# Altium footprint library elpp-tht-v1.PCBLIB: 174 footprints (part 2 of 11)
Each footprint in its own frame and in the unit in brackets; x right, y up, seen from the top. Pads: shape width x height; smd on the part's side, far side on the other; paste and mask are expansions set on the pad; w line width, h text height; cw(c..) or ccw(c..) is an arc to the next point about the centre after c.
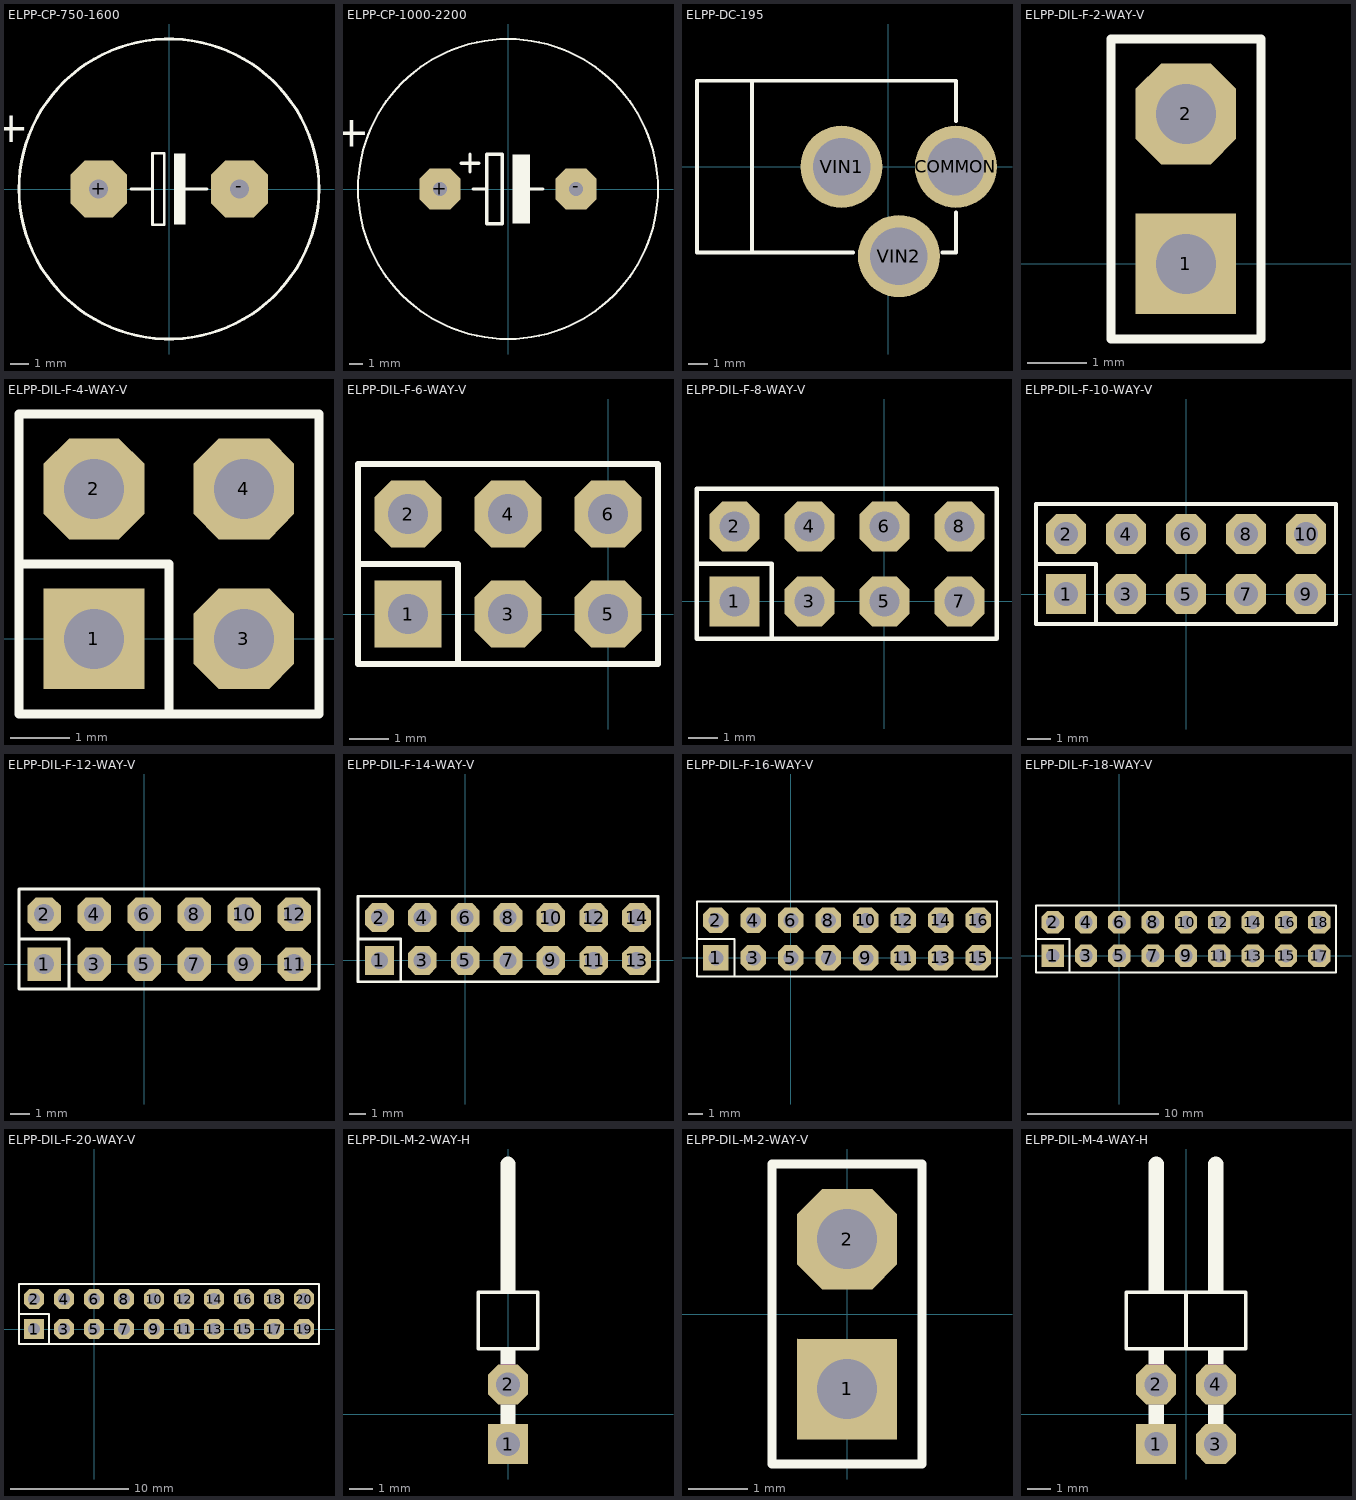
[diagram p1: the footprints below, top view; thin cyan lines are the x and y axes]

## ELPP-CP-750-1600 [mil]
pads (2):
  oct 119x119 hole 40: +(-147.64,0) -(148,0)
Top Overlay:
  circle w6: c0,0 r315
  rectangle: 10,-75 35,75
  lines w6: -80,0 -35,0 ; 25,0 80,0 ; -35,0 -35,75 -10,75 -10,-75 -35,-75 -35,0
  text "+" at -295,175 h108.5
Mechanical 2:
  text ">NAME" at -255,245 h42.5
Mechanical 4:
  text ">VALUE" at -150,-150 h42.5

## ELPP-CP-1000-2200 [mil]
pads (2):
  oct 119x119 hole 40: +(-196.85,0) -(197,0)
Top Overlay:
  circle w6: c0,0 r434
  rectangle: 13,-100 63,100
  lines w10: -135,75 -85,75 ; -110,50 -110,100 ; -100,0 -62,0 ; 25,0 100,0 ; -62,0 -62,100 -17,100 -17,-100 -62,-100 -62,0
  text "+" at -400,230 h155
Mechanical 2:
  text ">NAME" at -350,330 h42.5
Mechanical 4:
  text ">VALUE" at -150,-200 h42.5

## ELPP-DC-195 [mil]
pads (3):
  round 170 hole 119: COMMON(140,0) VIN1(-96.85,0) VIN2(22,-185.04)
Top Overlay:
  lines w8: -73.23,-177.17 -281.89,-177.17 ; 112,-177.17 140,-177.17 140,-94.49 ; 140,95 140,178 -281.89,178 ; -281.89,-177.17 -396.06,-177.17 -396.06,178 -281.89,178 ; -281.89,-177.17 -281.89,178
Mechanical 2:
  text ">NAME" at -200,200 h42.5
Mechanical 4:
  text ">VALUE" at -200,300 h42.5

## ELPP-DIL-F-2-WAY-V [mil]
pads (2):
  rect 67x67 hole 40: 1(-200,0)
  oct 67x67 hole 40: 2(-200,100)
Top Overlay:
  lines w6: -250,-50 -250,50 -250,150 -150,150 -150,-50 -250,-50
Mechanical 2:
  text ">NAME" at -250,185 h42.5
Mechanical 4:
  text ">VALUE" at -250,-135 h42.5
Mechanical 16:
  circle w16: c-200,100 r5
  circle w16: c-200,0 r5

## ELPP-DIL-F-4-WAY-V [mil]
pads (4):
  rect 67x67 hole 40: 1(-200,0)
  oct 67x67 hole 40: 2(-200,100) 3(-100,0) 4(-100,100)
Top Overlay:
  lines w6: -250,50 -250,-50 -150,-50 ; -250,50 -250,150 -50,150 -50,-50 -150,-50 ; -250,50 -150,50 -150,-50
Mechanical 2:
  text ">NAME" at -250,185 h42.5
Mechanical 4:
  text ">VALUE" at -250,-135 h42.5
Mechanical 16:
  circle w16: c-200,100 r5
  circle w16: c-200,0 r5
  circle w16: c-100,100 r5
  circle w16: c-100,0 r5

## ELPP-DIL-F-6-WAY-V [mil]
pads (6):
  rect 67x67 hole 40: 1(-200,0)
  oct 67x67 hole 40: 2(-200,100) 3(-100,0) 4(-100,100) 5(0,0) 6(0,100)
Top Overlay:
  lines w6: -250,50 -250,-50 -150,-50 ; -250,50 -250,150 50,150 50,-50 -150,-50 ; -250,50 -150,50 -150,-50
Mechanical 2:
  text ">NAME" at -250,185 h42.5
Mechanical 4:
  text ">VALUE" at -250,-135 h42.5
Mechanical 16:
  circle w16: c-200,100 r5
  circle w16: c-200,0 r5
  circle w16: c-100,100 r5
  circle w16: c-100,0 r5
  circle w16: c0,100 r5
  circle w16: c0,0 r5

## ELPP-DIL-F-8-WAY-V [mil]
pads (8):
  rect 67x67 hole 40: 1(-200,0)
  oct 67x67 hole 40: 2(-200,100) 3(-100,0) 4(-100,100) 5(0,0) 6(0,100) 7(100,0) 8(100,100)
Top Overlay:
  lines w6: -250,50 -250,-50 -150,-50 ; -250,50 -250,150 150,150 150,-50 -150,-50 ; -250,50 -150,50 -150,-50
Mechanical 2:
  text ">NAME" at -250,185 h42.5
Mechanical 4:
  text ">VALUE" at -250,-135 h42.5
Mechanical 16:
  circle w16: c-200,100 r5
  circle w16: c-200,0 r5
  circle w16: c-100,100 r5
  circle w16: c-100,0 r5
  circle w16: c0,100 r5
  circle w16: c0,0 r5
  circle w16: c100,100 r5
  circle w16: c100,0 r5

## ELPP-DIL-F-10-WAY-V [mil]
pads (10):
  rect 67x67 hole 40: 1(-200,0)
  oct 67x67 hole 40: 2(-200,100) 3(-100,0) 4(-100,100) 5(0,0) 6(0,100) 7(100,0) 8(100,100) 9(200,0) 10(200,100)
Top Overlay:
  lines w6: -250,50 -250,-50 -150,-50 ; -250,50 -250,150 250,150 250,-50 -150,-50 ; -250,50 -150,50 -150,-50
Mechanical 2:
  text ">NAME" at -250,185 h42.5
Mechanical 4:
  text ">VALUE" at -250,-135 h42.5
Mechanical 16:
  circle w16: c-200,100 r5
  circle w16: c-200,0 r5
  circle w16: c-100,100 r5
  circle w16: c-100,0 r5
  circle w16: c0,100 r5
  circle w16: c0,0 r5
  circle w16: c100,100 r5
  circle w16: c100,0 r5
  circle w16: c200,100 r5
  circle w16: c200,0 r5

## ELPP-DIL-F-12-WAY-V [mil]
pads (12):
  rect 67x67 hole 40: 1(-200,0)
  oct 67x67 hole 40: 2(-200,100) 3(-100,0) 4(-100,100) 5(0,0) 6(0,100) 7(100,0) 8(100,100) 9(200,0) 10(200,100) 11(300,0) 12(300,100)
Top Overlay:
  lines w6: -250,50 -250,-50 -150,-50 ; -250,50 -250,150 350,150 350,-50 -150,-50 ; -250,50 -150,50 -150,-50
Mechanical 2:
  text ">NAME" at -250,185 h42.5
Mechanical 4:
  text ">VALUE" at -250,-135 h42.5
Mechanical 16:
  circle w16: c-200,100 r5
  circle w16: c-200,0 r5
  circle w16: c-100,100 r5
  circle w16: c-100,0 r5
  circle w16: c0,100 r5
  circle w16: c0,0 r5
  circle w16: c100,100 r5
  circle w16: c100,0 r5
  circle w16: c200,100 r5
  circle w16: c200,0 r5
  circle w16: c300,100 r5
  circle w16: c300,0 r5

## ELPP-DIL-F-14-WAY-V [mil]
pads (14):
  rect 67x67 hole 40: 1(-200,0)
  oct 67x67 hole 40: 2(-200,100) 3(-100,0) 4(-100,100) 5(0,0) 6(0,100) 7(100,0) 8(100,100) 9(200,0) 10(200,100) 11(300,0) 12(300,100) 13(400,0) 14(400,100)
Top Overlay:
  lines w6: -250,50 -250,-50 -150,-50 ; -250,50 -250,150 450,150 450,-50 -150,-50 ; -250,50 -150,50 -150,-50
Mechanical 2:
  text ">NAME" at -250,185 h42.5
Mechanical 4:
  text ">VALUE" at -250,-135 h42.5
Mechanical 16:
  circle w16: c-200,100 r5
  circle w16: c-200,0 r5
  circle w16: c-100,100 r5
  circle w16: c-100,0 r5
  circle w16: c0,100 r5
  circle w16: c0,0 r5
  circle w16: c100,100 r5
  circle w16: c100,0 r5
  circle w16: c200,100 r5
  circle w16: c200,0 r5
  circle w16: c300,100 r5
  circle w16: c300,0 r5
  circle w16: c400,100 r5
  circle w16: c400,0 r5

## ELPP-DIL-F-16-WAY-V [mil]
pads (16):
  rect 67x67 hole 40: 1(-200,0)
  oct 67x67 hole 40: 2(-200,100) 3(-100,0) 4(-100,100) 5(0,0) 6(0,100) 7(100,0) 8(100,100) 9(200,0) 10(200,100) 11(300,0) 12(300,100) 13(400,0) 14(400,100) 15(500,0) 16(500,100)
Top Overlay:
  lines w6: -250,50 -250,-50 -150,-50 ; -250,50 -250,150 550,150 550,-50 -150,-50 ; -250,50 -150,50 -150,-50
Mechanical 2:
  text ">NAME" at -250,185 h42.5
Mechanical 4:
  text ">VALUE" at -250,-135 h42.5
Mechanical 16:
  circle w16: c-200,100 r5
  circle w16: c-200,0 r5
  circle w16: c-100,100 r5
  circle w16: c-100,0 r5
  circle w16: c0,100 r5
  circle w16: c0,0 r5
  circle w16: c100,100 r5
  circle w16: c100,0 r5
  circle w16: c200,100 r5
  circle w16: c200,0 r5
  circle w16: c300,100 r5
  circle w16: c300,0 r5
  circle w16: c400,100 r5
  circle w16: c400,0 r5
  circle w16: c500,100 r5
  circle w16: c500,0 r5

## ELPP-DIL-F-18-WAY-V [mil]
pads (18):
  rect 67x67 hole 40: 1(-200,0)
  oct 67x67 hole 40: 2(-200,100) 3(-100,0) 4(-100,100) 5(0,0) 6(0,100) 7(100,0) 8(100,100) 9(200,0) 10(200,100) 11(300,0) 12(300,100) 13(400,0) 14(400,100) 15(500,0) 16(500,100) 17(600,0) 18(600,100)
Top Overlay:
  lines w6: -250,50 -250,-50 -150,-50 ; -250,50 -250,150 650,150 650,-50 -150,-50 ; -250,50 -150,50 -150,-50
Mechanical 2:
  text ">NAME" at -250,185 h42.5
Mechanical 4:
  text ">VALUE" at -250,-135 h42.5
Mechanical 16:
  circle w16: c-200,100 r5
  circle w16: c-200,0 r5
  circle w16: c-100,100 r5
  circle w16: c-100,0 r5
  circle w16: c0,100 r5
  circle w16: c0,0 r5
  circle w16: c100,100 r5
  circle w16: c100,0 r5
  circle w16: c200,100 r5
  circle w16: c200,0 r5
  circle w16: c300,100 r5
  circle w16: c300,0 r5
  circle w16: c400,100 r5
  circle w16: c400,0 r5
  circle w16: c500,100 r5
  circle w16: c500,0 r5
  circle w16: c600,100 r5
  circle w16: c600,0 r5

## ELPP-DIL-F-20-WAY-V [mil]
pads (20):
  rect 67x67 hole 40: 1(-200,0)
  oct 67x67 hole 40: 2(-200,100) 3(-100,0) 4(-100,100) 5(0,0) 6(0,100) 7(100,0) 8(100,100) 9(200,0) 10(200,100) 11(300,0) 12(300,100) 13(400,0) 14(400,100) 15(500,0) 16(500,100) 17(600,0) 18(600,100) 19(700,0) 20(700,100)
Top Overlay:
  lines w6: -250,50 -250,-50 -150,-50 ; -250,50 -250,150 750,150 750,-50 -150,-50 ; -250,50 -150,50 -150,-50
Mechanical 2:
  text ">NAME" at -250,185 h42.5
Mechanical 4:
  text ">VALUE" at -250,-135 h42.5
Mechanical 16:
  circle w16: c-200,100 r5
  circle w16: c-200,0 r5
  circle w16: c-100,100 r5
  circle w16: c-100,0 r5
  circle w16: c0,100 r5
  circle w16: c0,0 r5
  circle w16: c100,100 r5
  circle w16: c100,0 r5
  circle w16: c200,100 r5
  circle w16: c200,0 r5
  circle w16: c300,100 r5
  circle w16: c300,0 r5
  circle w16: c400,100 r5
  circle w16: c400,0 r5
  circle w16: c500,100 r5
  circle w16: c500,0 r5
  circle w16: c600,100 r5
  circle w16: c600,0 r5
  circle w16: c700,100 r5
  circle w16: c700,0 r5

## ELPP-DIL-M-2-WAY-H [mil]
pads (2):
  rect 67x67 hole 40: 1(0,-50)
  oct 67x67 hole 40: 2(0,50)
Top Overlay:
  rectangle: -13,205 13,235
  rectangle: -13,84 13,110
  rectangle: -13,-16 13,16
  lines w6: -50,110 50,110 50,205 -50,205 -50,110
  lines w26: 0,235 0,420
Mechanical 2:
  text ">NAME" at -75,175 h42.5
Mechanical 4:
  text ">VALUE" at 75,125 h42.5
Mechanical 16:
  rectangle: -13,16 13,84
  rectangle: -13,-62 13,-16

## ELPP-DIL-M-2-WAY-V [mil]
pads (2):
  rect 67x67 hole 40: 1(0,-50)
  oct 67x67 hole 40: 2(0,50)
Top Overlay:
  lines w6: -50,-100 50,-100 50,100 -50,100 -50,-100
Mechanical 2:
  text ">NAME" at -50,125 h42.5
Mechanical 4:
  text ">VALUE" at -50,-175 h42.5
Mechanical 16:
  rectangle: -10,-60 10,-40
  rectangle: -10,40 10,60

## ELPP-DIL-M-4-WAY-H [mil]
pads (4):
  rect 67x67 hole 40: 1(-50,-50)
  oct 67x67 hole 40: 2(-50,50) 3(50,-50) 4(50,50)
Top Overlay:
  rectangle: -63,205 -37,235
  rectangle: 37,205 63,235
  rectangle: 37,84 63,110
  rectangle: -63,84 -37,110
  rectangle: -63,-16 -37,16
  rectangle: 37,-16 63,16
  lines w6: 0,110 0,205 ; 0,110 -100,110 -100,205 0,205 ; 0,110 100,110 100,205 0,205
  lines w26: -50,235 -50,420 ; 50,235 50,420
Mechanical 2:
  text ">NAME" at -125,175 h42.5
Mechanical 4:
  text ">VALUE" at 125,125 h42.5
Mechanical 16:
  rectangle: -63,16 -37,84
  rectangle: -63,-62 -37,-16
  rectangle: 37,16 63,84
  rectangle: 37,-62 63,-16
